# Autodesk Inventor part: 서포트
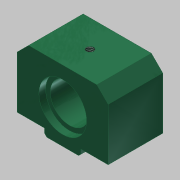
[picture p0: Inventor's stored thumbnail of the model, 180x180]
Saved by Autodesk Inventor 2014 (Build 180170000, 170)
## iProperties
Created: 2019-04
Part Number: 서포트
Material: 알루미늄 6061
Document SubType Name: Modeling
Designer: mduedu
Density: 1 g/cm^3
Appearance: 매끄러움 - 짙은 바다 녹색
Author: mduedu
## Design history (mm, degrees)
sketch "스케치1"
  geometry: L1 (3, 20)-(31, 20); L2 (31, 20)-(31, -20); L3 (31, -20)-(3, -20); L4 (0, -8)-(0, 8); L5 (0, 8)-(3, 8); L6 (3, 8)-(3, 20); L7 (0, 0)-(31, 0); L8 (0, -8)-(3, -8); L9 (3, -8)-(3, -20); 1 further point
  constraints: 18 end point, 3 symmetric about line, 2 horizontal, 2 midpoint, 2 parallel, 2 perpendicular, 1 coincident
  dimensions: "d3" = 31 distance between parallel lines of L4 L2; "d5" = 16 distance of L4.start L4.end; "d6" = 40 distance between parallel lines of L3 L1; "d7" = 3 distance between parallel lines of L4 L9
extrude "돌출1" new body sketch "스케치1" distance "d8" = 24; taper "d9" = 0 deg
chamfer "모따기1" distance "d10" = 5; stored, may be unused: second distance "d11" = 2, angle "d12" = 45 deg
chamfer "모따기2" distance "d13" = 1; stored, may be unused: second distance "d14" = 2, angle "d15" = 45 deg
sketch "스케치2"
  geometry: L1 (7, 0)-(-7, 0) reference; L2 (20, 3)-(8, 3) reference; 3 further points
  constraints: 1 midpoint, 1 vertical alignment
  dimensions: "d24" = 12 distance from line of point (0, 15) L2
hole "구멍1" sketch "스케치2" at (0, 15) diameter "d17" = 17; stored, may be unused: countersink angle "d21" = 90 deg, drill point angle "d23" = 118 deg; dims "d18" = 6, "d19" = 21, "d20" = 3, "d22" = 8
sketch "스케치3"
  geometry: L1 (0, 30)-(0, 0) reference; 3 further points
  constraints: 1 horizontal alignment, 1 midpoint
  dimensions: "d25" = 12 distance from line of point (12, 15) L1
hole "구멍2" sketch "스케치3" at (12, 15) diameter "d26" = 3.242; stored, may be unused: countersink angle "d30" = 90 deg, drill point angle "d32" = 118 deg; dims "d27" = 6, "d28" = 21, "d29" = 3, "d31" = 8
sketch "스케치4"
  geometry: L1 (0, -8)-(24, -8); L2 (24, 0.5)-(24, -16.5) reference; L3 (0, -28)-(0, -23) reference; 4 further points
  constraints: 2 end point, 2 symmetric about line, 1 horizontal, 1 horizontal alignment, 1 midpoint
  dimensions: "d33" = 6 distance from line of point (6, -22) L3; "d34" = 12 distance of point (18, -22) point (6, -22); "d35" = 28 distance of point (6, 6) point (6, -22); "d36" = 14 distance from line of point (6, -22) L1 (derived)
hole "구멍3" sketch "스케치4" at (6, -22), (18, -22), (18, 6), (6, 6) diameter "d37" = 3.242; stored, may be unused: countersink angle "d41" = 90 deg, drill point angle "d43" = 118 deg; dims "d38" = 9, "d39" = 21, "d40" = 3, "d42" = 11
node "솔리드1"
